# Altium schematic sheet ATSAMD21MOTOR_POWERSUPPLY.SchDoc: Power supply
size A3; Organization: ATMEL Norway; Address1: Vestre Rosten 79; Address2: N-7075 TILLER; Address3: NORWAY; DocumentNumber: A09-2130; Revision: 2; SheetNumber: 2; SheetTotal: 5; PageSetup: Record=PageOptions¦CenterHorizontal=True¦CenterVertical=True¦PrintScale=1.01¦XCorrection=1.00¦YCorrection=1.00¦PrintKind=1¦BorderSize=5000000¦LeftOffset=0¦BottomOffset=0¦Orientation=2¦PaperLength=1000¦PaperWidth=1000¦Scale=100¦PaperSource=7¦PrintQuality=-4¦MediaType=1¦DitherType=10¦PaperKind=A3 (297 x 420 mm)¦PrintScaleMode=1
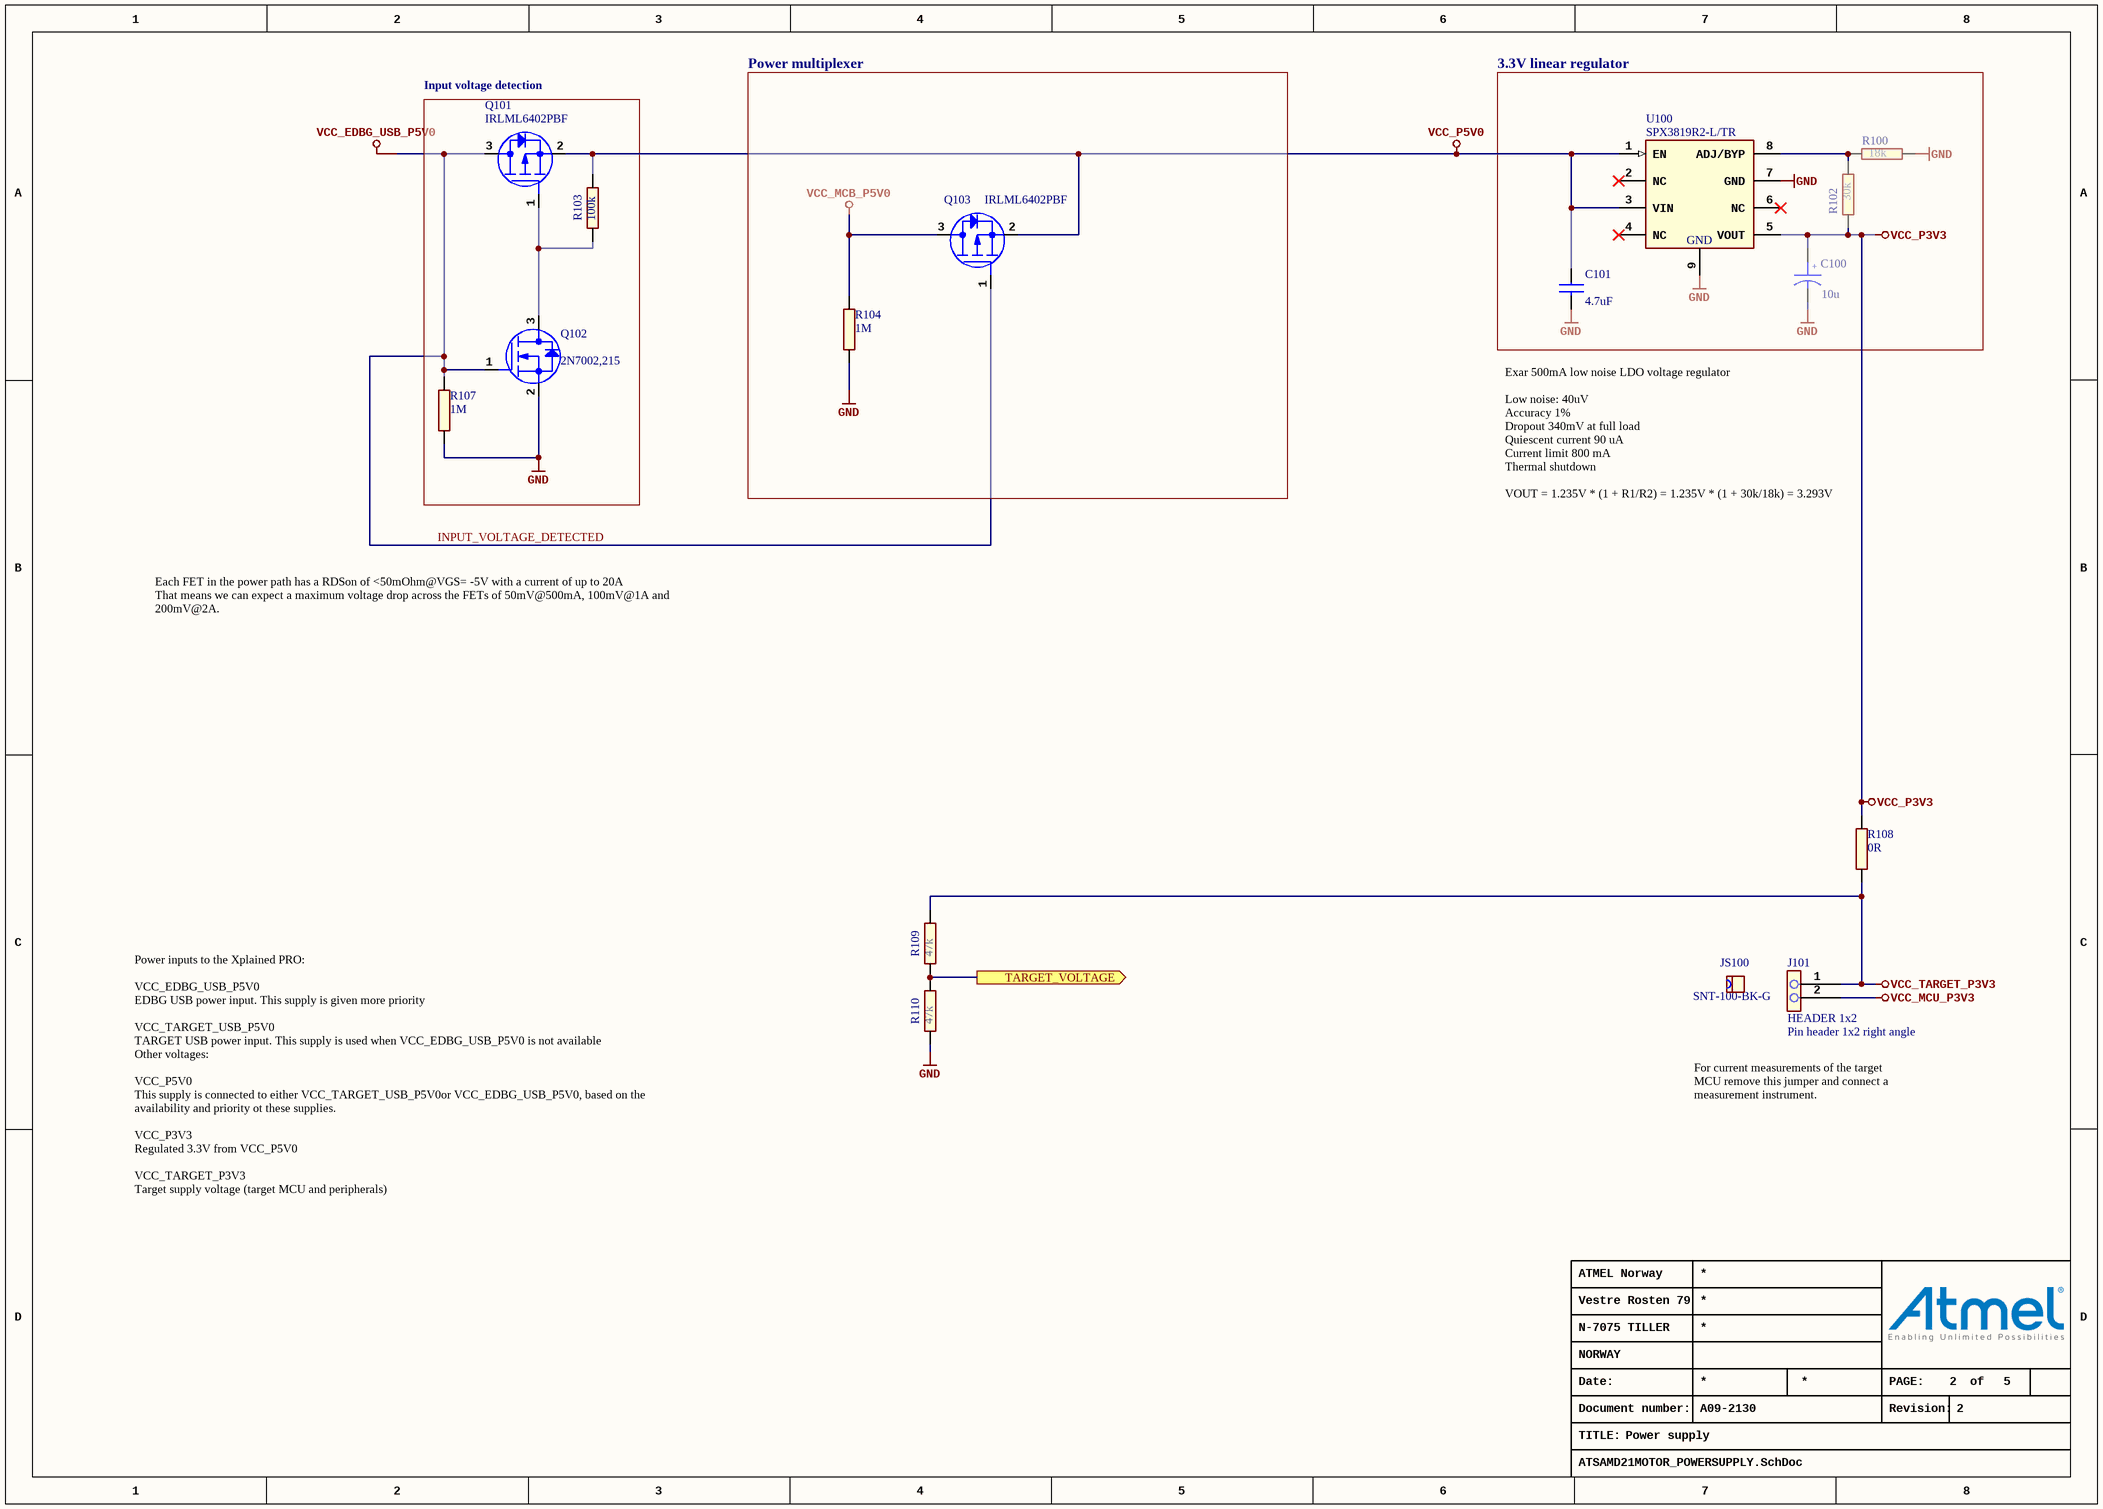
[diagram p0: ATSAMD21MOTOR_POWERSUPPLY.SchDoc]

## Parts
C100  value 10u  [AP1-00036]  (hidden comment: CAP-POL)
C101  value 4.7uF  [AP1-00039]  (hidden comment: CAP-NONPOL)
J101  HEADER 1x2  value Pin header 1x2 right angle  [AP8-00367]
JS100  value SNT-100-BK-G  [AP8-00525]  (hidden comment: To be used by request from ESCATEC)
Q101  value IRLML6402PBF  [AP5-00002]  (hidden comment: MOSFET_P_GSD)
Q102  value 2N7002,215  [AP5-00002]  (hidden comment: MOSFET_N_GSD)
Q103  value IRLML6402PBF  [AP5-00002]  (hidden comment: MOSFET_P_GSD)
R100  value 18k  [AP2-00000]  (hidden comment: R2)
R102  value 30k  [AP2-00000]  (hidden comment: R2)
R103  value 100k  [AP2-00000]  (hidden comment: R2)
R104  value 1M  [AP2-00000]  (hidden comment: R2)
R107  value 1M  [AP2-00000]  (hidden comment: R2)
R108  value 0R  [AP2-00000]  (hidden comment: R2)
R109  value 47k  [AP2-00000]  (hidden comment: R2)
R110  value 47k  [AP2-00000]  (hidden comment: R2)
U100  value SPX3819R2-L/TR  [AP6-00338]  (hidden comment: Mouser: 1016-1588-2-ND)

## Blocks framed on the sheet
Input voltage detection: Q101 Q102 R103 R107
Power multiplexer: Q103 R104
3.3V linear regulator: C100 C101 R100 R102 U100

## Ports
TARGET_VOLTAGE (out)

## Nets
GND: C100.2 C101.2 Q102.2(S) R100.2 R104.1 R107.1 R110.1 U100.7(GND) U100.9(GND)
INPUT_VOLTAGE_DETECTED: Q101.3(D) Q102.1(G) Q103.1(G) R107.2  [also labelled VCC_EDBG_USB_P5V0]
VCC_MCB_P5V0: Q103.3(D) R104.2
VCC_MCU_P3V3: J101.2
VCC_P3V3: C100.1 R102.1 R108.1 U100.5(VOUT)
VCC_P5V0: C101.1 Q101.2(S) Q103.2(S) R103.2 U100.1(EN) U100.3(VIN)
VCC_TARGET_P3V3: J101.1 R108.2 R109.2
TARGET_VOLTAGE: R109.1 R110.2 ; port TARGET_VOLTAGE
NetQ101_1: Q101.1(G) Q102.3(D) R103.1
NetR100_1: R100.1 R102.2 U100.8(ADJ/BYP)

Not connected (* = marked no-connect by the designer): U100 2(NC)* 4(NC)* 6(NC)*

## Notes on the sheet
- Exar 500mA low noise LDO voltage regulator
  Low noise: 40uV
  Accuracy 1%
  Dropout 340mV at full load
  Quiescent current 90 uA
  Current limit 800 mA
  Thermal shutdown
  VOUT = 1.235V * (1 + R1/R2) = 1.235V * (1 + 30k/18k) = 3.293V
- Each FET in the power path has a RDSon of <50mOhm@VGS= -5V with a current of up to 20A
  That means we can expect a maximum voltage drop across the FETs of 50mV@500mA, 100mV@1A and 200mV@2A.
- For current measurements of the target MCU remove this jumper and connect a measurement instrument.
- Power inputs to the Xplained PRO:
  VCC_EDBG_USB_P5V0
  EDBG USB power input. This supply is given more priority
  VCC_TARGET_USB_P5V0
  TARGET USB power input. This supply is used when VCC_EDBG_USB_P5V0 is not available
  Other voltages:
  VCC_P5V0
  This supply is connected to either VCC_TARGET_USB_P5V0or VCC_EDBG_USB_P5V0, based on the availability and priority ot these supplies.
  VCC_P3V3
  Regulated 3.3V from VCC_P5V0
  VCC_TARGET_P3V3
  Target supply voltage (target MCU and peripherals)

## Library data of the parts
C100 = A01-0324: SMD tantalum capacitor, ESR = 1.7, 3216-18 (EIA) 1206,; PartGroup: Capacitors,Tantalum; Manufacturer: vishay; MPN: TR3A106K016C1700; Tolerance: +-10%; TemperatureRange: -55°C ~ 85°C; ComponentStatus: 'Active (verified)'
C101 = A01-0377: Ceramic capacitor, SMD 0603, X5R, 10V, 10% (de31036); PartGroup: Capacitors,Ceramic,SMD 0603; Manufacturer: tdk; MPN: C1608X5R1A475K; TemperatureRange: -55 - +85 deg C; ComponentStatus: 'Active (verified)'
J101 = A08-0764: 1x2 pin header, right angle, 2.54 mm pitch, through-hole; PartGroup: Mechanical devices,Connectors,Pin headers; Manufacturer: Pro-data International Corp; MPN: 2213R-2G; ComponentStatus: 'Active (verified)'
JS100 = A08-0543: Jumper cap for 2.54mm pinheader; PartGroup: Mechanical devices,Mounting accessories,Other; Manufacturer: SAMTEC; ComponentStatus: 'Active (verified)'
Q101 Q103 = A05-0087: P-ch. MOSFET. -30V, -3.7A continuous,RDS(ON)=0.05Ohm@VGS=-4,5V, RDS(ON)=0.08Ohm@VGS=-2.5V; PartGroup: Transistors,Power FET,SMD; Manufacturer: International Rectifier; TemperatureRange: -55 - +150 deg C; ComponentStatus: 'Active (verified)'
Q102 = A05-0085: N-Channel MOSFET. 60V, 0.300A continuous, 1.2A Peak. RDS(ON) = 3.8Ohm@VGS=4.5V, VGS(th)<2.5V; PartGroup: Transistors,Small signal FET,SMD; Manufacturer: NXP; TemperatureRange: -65 to 150 deg C; ComponentStatus: 'New (not verified)'
R100 = A02-0242: Thick film resistor, SMD 0402, 1/16W, 1%; PartGroup: Resistors,SMD,0402 1%; TemperatureRange: -55 - +125 deg C; ComponentStatus: 'Active (verified)'
R102 = A02-0247: Thick film resistor, SMD 0402, 1/16W, 1%; PartGroup: Resistors,SMD,0402 1%; TemperatureRange: -55 - +125 deg C; ComponentStatus: 'Active (verified)'
R103 = A02-0260: Thick film resistor, SMD 0402, 1/16W, 1%; PartGroup: Resistors,SMD,0402 1%; TemperatureRange: -55 - +125 deg C; ComponentStatus: 'Active (verified)'
R104 = A02-0284: Thick film resistor, SMD 0402, 1/16W, 1%; PartGroup: Resistors,SMD,0402 1%; Manufacturer: KOA; MPN: RK73H1ETTP1004F; TemperatureRange: -55 - +125 deg C; ComponentStatus: 'Active (verified)'
R107 = A02-0284: Thick film resistor, SMD 0402, 1/16W, 1%; PartGroup: Resistors,SMD,0402 1%; TemperatureRange: -55 - +125 deg C; ComponentStatus: 'Active (verified)'
R108 = A02-0163: Thick film resistor, SMD 0402, 1/16W, 1%; PartGroup: Resistors,SMD,0402 1%; TemperatureRange: -55 - +125 deg C; ComponentStatus: 'Active (verified)'
R109 R110 = A02-0252: Thick film resistor, SMD 0402, 1/16W, 1%; PartGroup: Resistors,SMD,0402 1%; TemperatureRange: -55 - +125 deg C; ComponentStatus: 'Active (verified)'
U100 = A06-0957: 500mA LDO, ADJ, low noise, 8-DFN package; PartGroup: Integrated Circuits,Regulators,Linear; Manufacturer: Exar; Tolerance: ±1%; TemperatureRange: -40°C to +125°C; ComponentStatus: 'New (not verified)'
